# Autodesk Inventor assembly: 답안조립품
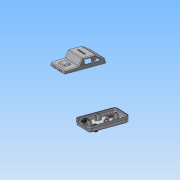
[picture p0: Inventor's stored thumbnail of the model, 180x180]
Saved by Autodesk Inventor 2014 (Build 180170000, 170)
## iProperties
Created: 2015-05
Part Number: 답안조립품
Document SubType Name: Assembly
Designer: Administrator
Author: Administrator
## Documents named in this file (5)
- C:\Documents and Settings\Administrator\바탕 화면\450507V1021\답안조립품.iam
- C:\Documents and Settings\Administrator\바탕 화면\450507V1021\1-본체.ipt
- C:\Documents and Settings\Administrator\바탕 화면\450507V1021\커버.ipt
- C:\Documents and Settings\Administrator\바탕 화면\450507V1021\바퀴고정부.ipt
- C:\Documents and Settings\Administrator\바탕 화면\450507V1021\바퀴.ipt
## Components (1 placed, 1 different names)
1. 1-본체:1
